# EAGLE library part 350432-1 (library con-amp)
Universal MATE-N-LOK .250" Centerline, 600 V, 19 - 36 A max Source: http://catalog.tycoelectronics.com/ .. ENG_CD_350432_W.pdf
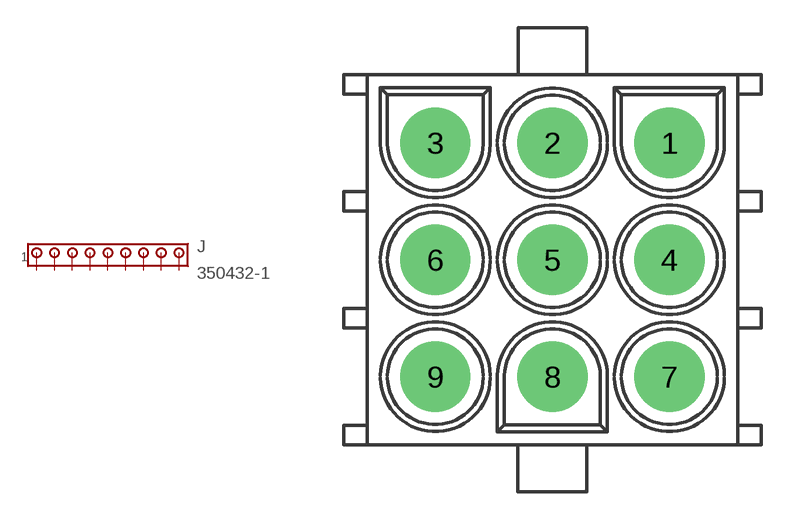
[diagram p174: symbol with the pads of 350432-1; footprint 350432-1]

Designator prefix J

## 350432-1 (MF: TYCO ELECTRONICS; MPN: 350432-1; OC_FARNELL: 285353; OC_NEWARK: 46F2055)  [350432-1]
1  1  pas
2  2  pas
3  3  pas
4  4  pas
5  5  pas
6  6  pas
7  7  pas
8  8  pas
9  9  pas

## Footprint 350432-1 (pad centres in mm)
Universal MATE-N-LOK .250" Centerline, 600 V, 19 - 36 A max Source: http://catalog.tycoelectronics.com/ .. ENG_CD_350432_W.pdf
drill 1.8 pad 3.81 round: 1 6.35,6.35; 2 0,6.35; 3 -6.35,6.35; 4 6.35,0; 5 0,0; 6 -6.35,0; 7 6.35,-6.35; 8 0,-6.35; 9 -6.35,-6.35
